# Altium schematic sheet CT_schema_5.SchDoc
size 334 x 183 mm
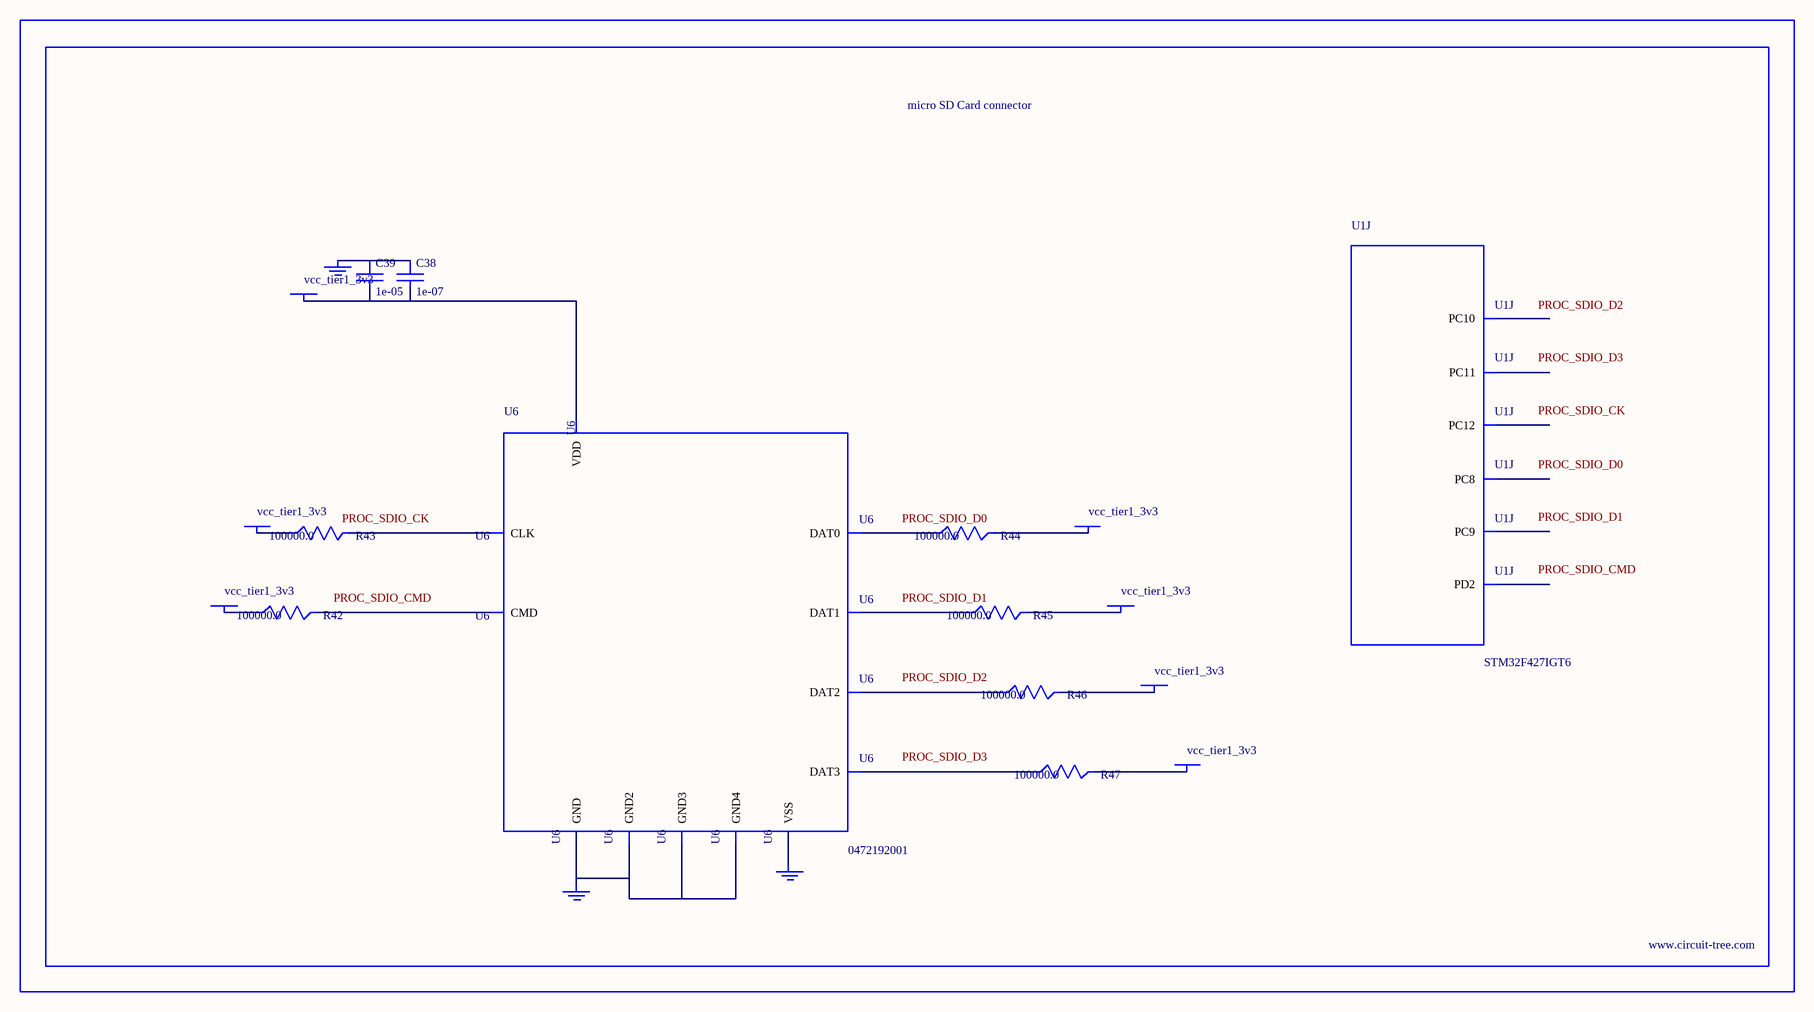
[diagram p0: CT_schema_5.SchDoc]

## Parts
BORDER4  (no value)
C38  1e-07  [C0402]
C39  1e-05  [C0805]
GND_INSTANCE_4_0  (no value)
GND_INSTANCE_4_1  (no value)
GND_INSTANCE_4_2  (no value)
POWER_INSTANCE_4_0  vcc_tier1_3v3
POWER_INSTANCE_4_1  vcc_tier1_3v3
POWER_INSTANCE_4_2  vcc_tier1_3v3
POWER_INSTANCE_4_3  vcc_tier1_3v3
POWER_INSTANCE_4_4  vcc_tier1_3v3
POWER_INSTANCE_4_5  vcc_tier1_3v3
POWER_INSTANCE_4_6  vcc_tier1_3v3
R42  100000.0  [R0603]
R43  100000.0  [R0603]
R44  100000.0  [R0603]
R45  100000.0  [R0603]
R46  100000.0  [R0603]
R47  100000.0  [R0603]
U1  STM32F427IGT6  [LQFP176]  (part J of 14)
U6  0472192001  [MOLEX_47219-2001]

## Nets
NetC38_1: C38.1 C39.1 GND_INSTANCE_4_0.0(GND)
NetC38_2: C38.2 C39.2 POWER_INSTANCE_4_3.0(PWR) U6.4(VDD)
NetGND_INSTANCE_4_1_0: GND_INSTANCE_4_1.0(GND) U6.6(VSS)
NetGND_INSTANCE_4_2_0: GND_INSTANCE_4_2.0(GND) U6.G1(GND) U6.G2(GND2) U6.G3(GND3) U6.G4(GND4)
NetPOWER_INSTANCE_4_0_0: POWER_INSTANCE_4_0.0(PWR) R46.2
NetPOWER_INSTANCE_4_1_0: POWER_INSTANCE_4_1.0(PWR) R47.2
NetPOWER_INSTANCE_4_2_0: POWER_INSTANCE_4_2.0(PWR) R42.1
NetPOWER_INSTANCE_4_4_0: POWER_INSTANCE_4_4.0(PWR) R43.1
NetPOWER_INSTANCE_4_5_0: POWER_INSTANCE_4_5.0(PWR) R44.2
NetPOWER_INSTANCE_4_6_0: POWER_INSTANCE_4_6.0(PWR) R45.2
NetR42_2: R42.2 U6.3(CMD)
NetR43_2: R43.2 U6.5(CLK)
NetR44_1: R44.1 U6.7(DAT0)
NetR45_1: R45.1 U6.8(DAT1)
NetR46_1: R46.1 U6.1(DAT2)
NetR47_1: R47.1 U6.2(DAT3)

Not connected (* = marked no-connect by the designer): U1 117(PC8) 118(PC9) 139(PC10) 140(PC11) 141(PC12) 144(PD2)

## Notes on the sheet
- Labels drawn without touching a wire or pin: PROC_SDIO_CK, PROC_SDIO_CMD, PROC_SDIO_D0, PROC_SDIO_D1, PROC_SDIO_D2, PROC_SDIO_D3

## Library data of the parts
BORDER4 = BORDER_PAGE4
C38 = C0402C104K3RACTU
C39 = C0805C106K8RACTU
GND_INSTANCE_4_0-GND_INSTANCE_4_2 = GND
POWER_INSTANCE_4_0-POWER_INSTANCE_4_6 = PWR
R42-R47 = RC0603JR-07100KL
